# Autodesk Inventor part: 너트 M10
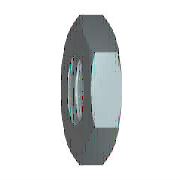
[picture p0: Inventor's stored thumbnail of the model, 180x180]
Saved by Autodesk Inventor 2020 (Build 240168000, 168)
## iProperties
IsCustomPart: 1
Created: 2012-02
Part Number: 너트 M10
Material: 스테인리스강
Description: 미터법 정밀 피치 스레드가 있는 6각 가는 너트(모따기됨)
Document SubType Name: Modeling
Standard: ISO 8675
Designer: mduedu
Standard Revision: Second edition 1999-08-15
Standards Organization: ISO
Language: ko-KR
Size Designation: M10 x 1
Categories: <MemberInstance><Categories><Category DisplayName="조임쇠" InternalName="e4da775c-781d-43d5-af7c-5136215cf5a6" Mnemonic="FSTN"><Category DisplayName="너트" InternalN
Density: 8.08 g/cm^3
Appearance: 기본값
Author: mduedu
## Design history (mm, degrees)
sketch "스케치1"
  geometry: L1 (-9.238, 0)-(-4.619, 8); L2 (-4.619, 8)-(4.619, 8); L3 (4.619, 8)-(9.238, 0); L4 (9.238, 0)-(4.619, -8); L5 (4.619, -8)-(-4.619, -8); L6 (-4.619, -8)-(-9.238, 0); 2 further points
  constraints: 12 end point, 1 coincident, 1 horizontal, 11 other
  dimensions: "d0" = 18.47521 distance of L3.end L1.start (= 1.1547 x SW)
extrude "본체" new body sketch "스케치1" distance "d1" = 5 (= KOH); taper "d2" = 0 deg
sketch "스케치2"
  geometry: L1 (0, 4.619)-(0, 9.238) reference; L2 (0, 9.238)-(5, 9.238) reference; L3 (5, 4.619)-(5, 9.238) reference; L4 (-1, 0)-(6, 0) reference; L5 (1.11, 9.238)-(0, 7.315); L6 (3.89, 9.238)-(5, 7.315)
  constraints: 4 end point, 4 point on line
  dimensions: "d3" = 30 deg angle of L1 L5 (= ANG1); "d4" = 30 deg angle of L3 L6 (= ANG2); "d5" = 14.63 diameter of L5.end L4 (= SW0); "d6" = 14.63 diameter of L6.end L4 (= SW01)
revolve "모따기1" sketch "스케치2" stored, may be unused: angle "d7" = 90 deg
sketch "스케치3"
  geometry: 4 further points
  constraints: 1 coincident, 1 other
hole "스레드" sketch "스케치3" at (0, 0) diameter "d25" = 8.91747; stored, may be unused: countersink angle "d29" = 82 deg, drill point angle "d31" = 118 deg; dims "d26" = 6, "d27" = 4, "d28" = 2, "d30" = 8
workaxis "Work Axis1"
workplane "Work Plane1"
body "Solid1"
chamfer "모따기2" distance "d8" = 0.54127 (= -0.5 x GD1 + 0.5 x NND); stored, may be unused: angle "d9" = 30 deg, second distance "d40" = 0.54127 (= -0.5 x GD1 + 0.5 x NND)
chamfer "모따기3" distance "d10" = 0.54127 (= -0.5 x GD1 + 0.5 x NND); stored, may be unused: angle "d11" = 30 deg, second distance "d41" = 0.54127 (= -0.5 x GD1 + 0.5 x NND)
other parameters: "ANG1" = 30 deg [user parameter; used in 1 equation term], "ANG2" = 30 deg [user parameter; used in 1 equation term], "KOH" = 5 [user parameter; used in 1 equation term], "SW" = 16 [user parameter; used in 1 equation term], "SW0" = 14.63 [user parameter; used in 2 equation terms], "SW01" = 14.63 (= SW0) [user parameter; used in 1 equation term], "GD1" = 8.91747 (computed from THREADDIA, PTC, TOA) [user parameter; used in 4 equation terms], "d13" = 0, "d14" = 0, "d39" = 0, "d42" = 0, "GUL" = 0.54127 (= 0.541266 x PTC) [user parameter], "TOA" = 30 deg [user parameter; used in 1 equation term], "PTC" = 1 [user parameter; used in 4 equation terms], "E0" = 17.77 [user parameter], "GAL" = 0.54127 (= 0.541266 x PTC) [user parameter]
